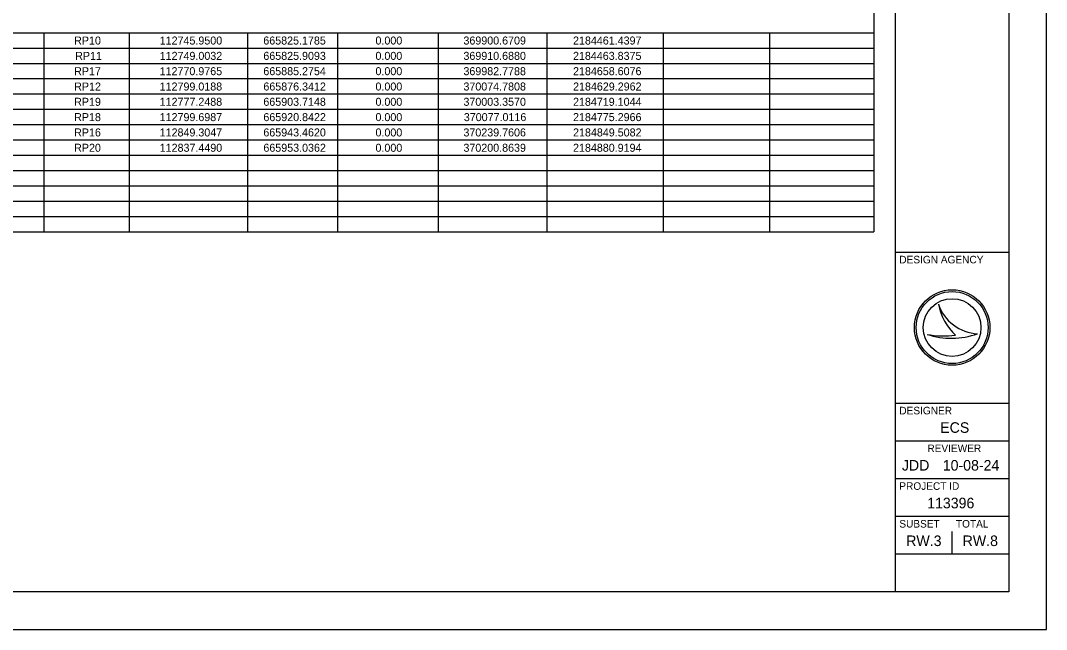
# Model space of a CAD drawing. Extents: x 0 to 680, y 0 to 440.
# Drawn here: x 408.1 to 680, y 0 to 161.3 of the extents above; entities that cross this region are included whole.
import ezdxf

# ---------------------------------------------------------------- set-up
doc = ezdxf.new("R2010")
doc.units = 0
for name, color, linetype in [('SH_Border', 7, 'Continuous'), ('SH_Cut_Line', 7, 'Continuous'), ('SH_Data', 7, 'Continuous'), ('SH_Text', 7, 'Continuous')]:
    doc.layers.add(name, color=color, linetype=linetype)

msp = doc.modelspace()

# ---------------------------------------------------------------- linework, layer by layer
at = {"layer": 'SH_Border'}
for p, q in [((640, 10), (640, 430)), ((640, 100), (670, 100)), ((640, 60), (670, 60)), ((640, 50), (670, 50)), ((640, 40), (670, 40)), ((640, 30), (670, 30)), ((640, 20), (670, 20))]:
    msp.add_line(p, q, dxfattribs=at)
msp.add_lwpolyline([(30, 430), (670, 430), (670, 10), (30, 10)], close=True, dxfattribs=at)
at = {"layer": 'SH_Cut_Line'}
msp.add_lwpolyline([(0, 0), (680, 0), (680, 440), (0, 440)], close=True, dxfattribs=at)
at = {"layer": 'SH_Data'}
for p, q in [((651.35, 86.19), (651.35, 86.19)), ((655, 80), (655, 80)), ((648.34, 78.19), (648.34, 78.19)), ((661.75, 78.37), (661.75, 78.37)), ((655, 20), (655, 26))]:
    msp.add_line(p, q, dxfattribs=at)
for radius in [10, 9.54, 9.54, 7.64]:
    msp.add_circle((655, 80), radius, dxfattribs=at)
for centre, radius, start, end in [((662.32, 89.95), 11.6, 198.9257, 198.9319), ((666.93, 89.4), 15.91, 191.6379, 191.6421), ((662.32, 89.95), 11.6, 198.9319, 267.1657), ((666.93, 89.4), 15.91, 191.6421, 226.0947), ((654.79, 97.4), 20.26, 251.4576, 290.0832), ((652.96, 103.09), 25.32, 259.4964, 259.4995), ((654.79, 97.4), 20.26, 251.4527, 251.4576), ((652.96, 103.09), 25.32, 259.4995, 276.6672)]:
    msp.add_arc(centre, radius, start, end, dxfattribs=at)
at = {"layer": 'SH_Text'}
for p, q in [((634.27, 217.51), (634.27, 113.48)), ((231.79, 158.11), (436.91, 158.11)), ((414.22, 158.11), (414.22, 113.48)), ((436.91, 158.11), (634.27, 158.11)), ((436.91, 158.11), (436.91, 113.48)), ((468.27, 158.11), (468.27, 113.48)), ((492.06, 158.11), (492.06, 113.48)), ((518.81, 158.11), (518.81, 113.48)), ((547.58, 158.11), (547.58, 113.48)), ((578.38, 158.11), (578.38, 113.48)), ((606.61, 158.11), (606.61, 113.48)), ((231.79, 154.06), (436.91, 154.06)), ((436.91, 154.06), (634.27, 154.06)), ((231.79, 150), (436.91, 150)), ((436.91, 150), (634.27, 150)), ((231.79, 145.94), (436.91, 145.94)), ((436.91, 145.94), (634.27, 145.94)), ((231.79, 141.88), (436.91, 141.88)), ((436.91, 141.88), (634.27, 141.88)), ((231.79, 137.82), (436.91, 137.82)), ((436.91, 137.82), (634.27, 137.82)), ((231.79, 133.77), (436.91, 133.77)), ((436.91, 133.77), (634.27, 133.77)), ((231.79, 129.71), (436.91, 129.71)), ((436.91, 129.71), (634.27, 129.71)), ((231.79, 125.65), (436.91, 125.65)), ((436.91, 125.65), (634.27, 125.65)), ((231.79, 121.59), (436.91, 121.59)), ((436.91, 121.59), (634.27, 121.59)), ((231.79, 117.53), (436.91, 117.53)), ((436.91, 117.53), (634.27, 117.53)), ((231.79, 113.48), (436.91, 113.48)), ((414.22, 113.48), (414.22, 109.42)), ((436.91, 113.48), (634.27, 113.48)), ((436.91, 113.48), (436.91, 109.42)), ((468.27, 113.48), (468.27, 109.42)), ((492.06, 113.48), (492.06, 109.42)), ((518.81, 113.48), (518.81, 109.42)), ((547.58, 113.48), (547.58, 109.42)), ((578.38, 113.48), (578.38, 109.42)), ((606.61, 113.48), (606.61, 109.42)), ((634.27, 113.48), (634.27, 109.42)), ((231.79, 109.42), (436.91, 109.42)), ((414.22, 109.42), (414.22, 105.36)), ((436.91, 109.42), (634.27, 109.42)), ((436.91, 109.42), (436.91, 105.36)), ((468.27, 109.42), (468.27, 105.36)), ((492.06, 109.42), (492.06, 105.36)), ((518.81, 109.42), (518.81, 105.36)), ((547.58, 109.42), (547.58, 105.36)), ((578.38, 109.42), (578.38, 105.36)), ((606.61, 109.42), (606.61, 105.36)), ((634.27, 109.42), (634.27, 105.36)), ((231.79, 105.36), (436.91, 105.36)), ((436.91, 105.36), (634.27, 105.36))]:
    msp.add_line(p, q, dxfattribs=at)

# ---------------------------------------------------------------- texts
at = {"layer": 'SH_Data'}
for s, height, p in [('DESIGN AGENCY', 2, (641, 97)), ('DESIGNER', 2, (641, 57)), ('ECS', 2.8, (651.84, 52.1)), ('REVIEWER', 2, (648.44, 47)), ('JDD', 2.8, (641.68, 42.1)), ('10-08-24', 2.8, (652.51, 42.1)), ('PROJECT ID', 2, (641, 37)), ('113396', 2.8, (648.38, 32.1)), ('SUBSET', 2, (641, 27)), ('TOTAL', 2, (656, 27)), ('RW.3', 2.8, (642.82, 22.1)), ('RW.8', 2.8, (657.78, 22.1))]:
    msp.add_text(s, height=height, dxfattribs=at).set_placement(p)
at = {"layer": 'SH_Text'}
for s, height, p in [('RP10', 2.121, (422.29, 154.98)), ('112745.9500', 2.1212, (444.97, 154.98)), ('665825.1785', 2.1212, (472.43, 154.98)), ('0.000', 2.121, (502.16, 154.98)), ('369900.6709', 2.1212, (525.47, 154.98)), ('2184461.4397', 2.1212, (554.52, 154.98)), ('RP11', 2.121, (422.57, 150.92)), ('112749.0032', 2.1212, (444.97, 150.92)), ('665825.9093', 2.1212, (472.44, 150.92)), ('0.000', 2.121, (502.16, 150.92)), ('369910.6880', 2.1212, (525.47, 150.92)), ('2184463.8375', 2.1212, (554.51, 150.92)), ('RP17', 2.121, (422.29, 146.86)), ('112770.9765', 2.1212, (444.95, 146.86)), ('665885.2754', 2.1212, (472.44, 146.86)), ('0.000', 2.121, (502.16, 146.86)), ('369982.7788', 2.1212, (525.47, 146.86)), ('2184658.6076', 2.1212, (554.52, 146.86)), ('RP12', 2.121, (422.3, 142.8)), ('112799.0188', 2.1212, (444.96, 142.8)), ('665876.3412', 2.1212, (472.45, 142.8)), ('0.000', 2.121, (502.16, 142.8)), ('370074.7808', 2.1212, (525.47, 142.8)), ('2184629.2962', 2.1212, (554.53, 142.8)), ('RP19', 2.121, (422.29, 138.75)), ('112777.2488', 2.1212, (444.96, 138.75)), ('665903.7148', 2.1212, (472.44, 138.75)), ('0.000', 2.121, (502.16, 138.75)), ('370003.3570', 2.1212, (525.47, 138.75)), ('2184719.1044', 2.1212, (554.52, 138.75)), ('RP18', 2.121, (422.29, 134.69)), ('112799.6987', 2.1212, (444.96, 134.69)), ('665920.8422', 2.1212, (472.45, 134.69)), ('0.000', 2.121, (502.16, 134.69)), ('370077.0116', 2.1212, (525.57, 134.69)), ('2184775.2966', 2.1212, (554.52, 134.69)), ('RP16', 2.121, (422.29, 130.63)), ('112849.3047', 2.1212, (444.96, 130.63)), ('665943.4620', 2.1212, (472.44, 130.63)), ('0.000', 2.121, (502.16, 130.63)), ('370239.7606', 2.1212, (525.47, 130.63)), ('2184849.5082', 2.1212, (554.53, 130.63)), ('RP20', 2.121, (422.29, 126.57)), ('112837.4490', 2.1212, (444.97, 126.57)), ('665953.0362', 2.1212, (472.45, 126.57)), ('0.000', 2.121, (502.16, 126.57)), ('370200.8639', 2.1212, (525.47, 126.57)), ('2184880.9194', 2.1212, (554.52, 126.57))]:
    msp.add_text(s, height=height, dxfattribs=at).set_placement(p)

doc.saveas('drawing.dxf')
